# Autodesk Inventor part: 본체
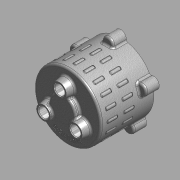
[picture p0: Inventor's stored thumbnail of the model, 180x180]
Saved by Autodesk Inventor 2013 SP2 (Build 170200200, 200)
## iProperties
Created: 2015-11
Part Number: 본체
Document SubType Name: 모델링
Designer: mdu
Material: 알루미늄 6061
Density: 1 g/cm^3
변환 표준: STEP AP214IS
파일 이름: C:\Users\SeoGD\Desktop\?쒗뿕\紐몄껜.stp
전처리기: Build: 253, Release: 2010 SP1 - Date: Wed 07/29/2009
전송 단위: 밀리미터
불확실성: 0.01
Author: mdu
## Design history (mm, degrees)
sketch "스케치2"
  geometry: C1 r 50 at (0, 0); 1 further point
  constraints: 1 centre point, 1 coincident
  dimensions: "d9" = 100 diameter of C1
extrude "돌출2" new body sketch "스케치2" distance "d10" = 80; taper "d11" = 0 deg
feature "쉘1" dims "d12" = 5
sketch "스케치3" dims "d13" = 55
  geometry: C1 r 7.5 at (0, 27.5); C2 r 12.5 at (0, 27.5); 2 further points
  constraints: 2 centre point, 2 coincident, 2 vertical alignment, 2 other
  dimensions: "d14" = 15 diameter of C1; "d15" = 25 diameter of C2
extrude "돌출3" join sketch "스케치3" distance "d16" = 12; taper "d17" = -10 deg
hole "구멍2" diameter "d20" = 15; stored, may be unused: countersink angle "d24" = 90 deg, drill point angle "d26" = 118 deg; dims "d18" = 10, "d19" = 10, "d21" = 6, "d22" = 4, "d23" = 2, "d25" = 15
chamfer "모따기1" distance "d27" = 1; stored, may be unused: second distance "d28" = 2, angle "d29" = 45 deg
sketch "스케치4"
  geometry: L1 (0, 0)-(0, 88); L2 (0, 70)-(13.16, 70); L3 (-45, 75)-(45, 75) reference; L4 (-50, 80)-(50, 80) reference; L5 (13.16, 70)-(14.5, 75); L6 (20, 80)-(20, 88); L7 (20, 88)-(0, 88); L8 (20, 80)-(14.5, 75)
  constraints: 12 end point, 3 point on line, 2 perpendicular, 1 vertical
  dimensions: "d34" = 40 diameter of L6 L1; "d35" = 105 deg angle of L5 L3; "d36" = 5 distance between parallel lines of L2 L3; "d37" = 8 distance between parallel lines of L7 L4; "d51" = 29 diameter of L5.end L1
revolve "회전1" sketch "스케치4" stored, may be unused: angle "d38" = 90 deg
hole "구멍3" diameter "d41" = 15; stored, may be unused: countersink angle "d45" = 90 deg, drill point angle "d47" = 0 deg; dims "d39" = 10, "d40" = 10, "d42" = 6, "d43" = 22, "d44" = 13, "d46" = 15
chamfer "모따기2" distance "d48" = 1; stored, may be unused: second distance "d49" = 2, angle "d50" = 45 deg
fillet "모깎기1" dims "d52" = 3
fillet "모깎기2" dims "d53" = 3, "d72" = 0.2
sketch "스케치5"
  geometry: A1 r 50 centre (0, 0) between (50, 0) and (-8.074, 49.344) reference; A2 r 8.5 centre (0, 52) between (8.074, 49.344) and (-8.074, 49.344); 1 further point
  constraints: 5 point on circle, 1 centre point, 1 horizontal alignment
  dimensions: "d54" = 90 deg dimension on point (0, 0) A2.centre A1.start; "d55" = 52 distance of A2.centre point (0, 0); "d56" = 17 diameter of A2
extrude "돌출4" join sketch "스케치5" distance "d57" = 20; taper "d58" = 0 deg
fillet "모깎기3" dims "d59" = 3
hole "구멍4" diameter "d62" = 4.134; stored, may be unused: countersink angle "d66" = 90 deg, drill point angle "d68" = 118 deg; dims "d60" = 10, "d61" = 10, "d63" = 12, "d64" = 22, "d65" = 13, "d67" = 15
sketch "스케치6"
  geometry: C1 r 47 at (0, 0) reference; C2 r 42.5 at (0, 0); 1 further point
  constraints: 1 centre point, 1 coincident, 1 other
  dimensions: "d73" = 85 diameter of C2
feature "엠보싱1" sketch "스케치6" dims "d74" = 0.5, "d75" = 0
node "작업 평면1"
sketch "스케치7"
  geometry: A1 r 50 centre (0, 0) between (5.144, 49.735) and (-5.144, 49.735) reference; A2 r 3 centre (0, 47.916) between (2.204, 49.951) and (-2.204, 49.951); 1 further point
  constraints: 4 point on circle, 1 centre point, 1 vertical alignment
  dimensions: "d77" = 3 radius of A2
extrude "돌출5" join sketch "스케치7" distance "d79" = 15; taper "d80" = 0 deg
fillet "모깎기4" dims "d81" = 1
fillet "모깎기5" dims "d82" = 1
node "솔리드1"
node "솔리드 본체"
node "곡면 본체"
pattern_circular "원형 패턴1" dims "d31" = 360 deg
pattern_circular "원형 패턴2" dims "d70" = 360 deg
pattern_circular "원형 패턴3" dims "d84" = 360 deg
pattern_linear "직사각형 패턴1" dims "d89" = 25
node "솔리드2"
